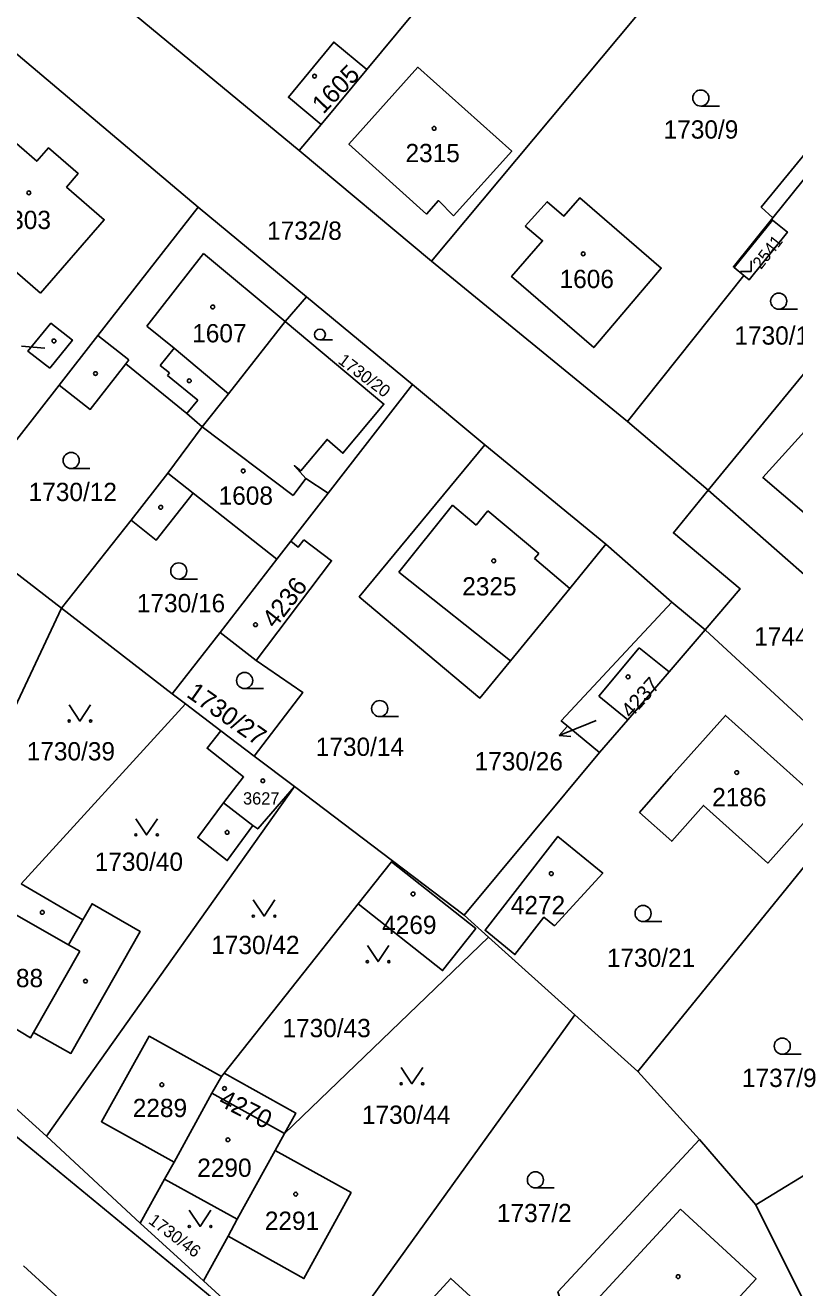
# Model space of a CAD drawing. Extents: x -679220 to -673243, y -1075091 to -1066557.
# Drawn here: x -676820 to -676748.4, y -1072173.6 to -1072056.2 of the extents above; entities that cross this region are included whole.
import ezdxf

# ---------------------------------------------------------------- set-up
doc = ezdxf.new("R2010")
doc.units = 0
for name, color, linetype in [('Hranice parcel', 7, 'Continuous'), ('Parcelní čísla', 7, 'Continuous'), ('Pop  PČ popisy', 7, 'Continuous'), ('Vnitřní kresba', 7, 'Continuous'), ('Značky budov', 7, 'Continuous'), ('Značky kultur', 7, 'Continuous')]:
    doc.layers.add(name, color=color, linetype=linetype)

msp = doc.modelspace()

# ---------------------------------------------------------------- linework, layer by layer
at = {"layer": 'Hranice parcel'}
for p, q in [((-676788.19, -1072060.27), (-676771.27, -1072039.91)), ((-676817.98, -1072048.36), (-676794.47, -1072067.82)), ((-676758.23, -1072049.49), (-676782.15, -1072078.09)), ((-676803.88, -1072073.07), (-676823.88, -1072056.2)), ((-676792.44, -1072065.38), (-676788.19, -1072060.27)), ((-676794.47, -1072067.82), (-676792.44, -1072065.38)), ((-676782.15, -1072078.09), (-676794.47, -1072067.82)), ((-676756.41, -1072099.41), (-676731.81, -1072069.41)), ((-676793.78, -1072081.41), (-676803.88, -1072073.07)), ((-676782.15, -1072078.09), (-676763.93, -1072093.01)), ((-676753.99, -1072078.69), (-676753.11, -1072079.43)), ((-676763.93, -1072093.01), (-676753.11, -1072079.43)), ((-676795.79, -1072083.71), (-676793.78, -1072081.41)), ((-676783.94, -1072089.58), (-676793.78, -1072081.41)), ((-676816.81, -1072089.62), (-676826.85, -1072102.46)), ((-676783.94, -1072089.58), (-676791.77, -1072099.66)), ((-676777.21, -1072095.19), (-676783.94, -1072089.58)), ((-676763.93, -1072093.01), (-676756.41, -1072099.41)), ((-676765.93, -1072104.41), (-676777.21, -1072095.19)), ((-676795.25, -1072104.15), (-676791.77, -1072099.66)), ((-676741.94, -1072112.1), (-676756.41, -1072099.41)), ((-676816.58, -1072110.38), (-676810.12, -1072102.18)), ((-676796.54, -1072105.8), (-676795.25, -1072104.15)), ((-676759.8, -1072109.8), (-676765.93, -1072104.41)), ((-676823.82, -1072104.8), (-676816.58, -1072110.38)), ((-676801.84, -1072112.62), (-676796.54, -1072105.8)), ((-676826.54, -1072131.48), (-676816.58, -1072110.38)), ((-676806.29, -1072118.35), (-676816.58, -1072110.38)), ((-676756.69, -1072112.4), (-676759.8, -1072109.8)), ((-676806.29, -1072118.35), (-676801.84, -1072112.62)), ((-676798.47, -1072115.23), (-676801.84, -1072112.62)), ((-676756.69, -1072112.4), (-676760.05, -1072116.28)), ((-676756.69, -1072112.4), (-676746.59, -1072121.71)), ((-676766.59, -1072118.56), (-676762.84, -1072114.06)), ((-676762.84, -1072114.06), (-676760.05, -1072116.28)), ((-676760.05, -1072116.28), (-676763.9, -1072120.74)), ((-676805.06, -1072119.28), (-676806.29, -1072118.35)), ((-676763.9, -1072120.74), (-676766.59, -1072118.56)), ((-676820.33, -1072136.02), (-676805.06, -1072119.28)), ((-676801.77, -1072121.78), (-676805.06, -1072119.28)), ((-676763.9, -1072120.74), (-676766.54, -1072123.79)), ((-676801.77, -1072121.78), (-676798.65, -1072124.14)), ((-676798.65, -1072124.14), (-676794.91, -1072126.97)), ((-676779.12, -1072138.92), (-676766.54, -1072123.79)), ((-676762.97, -1072153.46), (-676741.21, -1072126.67)), ((-676817.98, -1072159.47), (-676794.91, -1072126.97)), ((-676785.8, -1072133.86), (-676794.91, -1072126.97)), ((-676788.98, -1072137.87), (-676785.88, -1072133.96)), ((-676785.88, -1072133.96), (-676785.8, -1072133.86)), ((-676779.12, -1072138.92), (-676785.8, -1072133.86)), ((-676793.27, -1072182.15), (-676848.37, -1072136.87)), ((-676801.46, -1072153.6), (-676788.98, -1072137.87)), ((-676776.86, -1072140.96), (-676779.12, -1072138.92)), ((-676776.86, -1072140.96), (-676795.85, -1072159.22)), ((-676768.83, -1072148.2), (-676776.86, -1072140.96)), ((-676793.27, -1072182.15), (-676768.83, -1072148.2)), ((-676762.97, -1072153.46), (-676768.83, -1072148.2)), ((-676751.97, -1072165.85), (-676723.6, -1072148.5)), ((-676817.98, -1072159.47), (-676828.45, -1072150.07)), ((-676802.59, -1072155.49), (-676801.71, -1072153.92)), ((-676801.71, -1072153.92), (-676801.46, -1072153.6)), ((-676757.22, -1072159.8), (-676762.97, -1072153.46)), ((-676806.12, -1072161.88), (-676802.59, -1072155.49)), ((-676795.85, -1072159.22), (-676802.59, -1072155.49)), ((-676809.27, -1072167.56), (-676817.98, -1072159.47)), ((-676796.72, -1072160.8), (-676795.85, -1072159.22)), ((-676751.97, -1072165.85), (-676757.22, -1072159.8)), ((-676800.24, -1072167.19), (-676796.72, -1072160.8)), ((-676806.12, -1072161.88), (-676807, -1072163.46)), ((-676809.27, -1072167.56), (-676807, -1072163.46)), ((-676807, -1072163.46), (-676800.24, -1072167.19)), ((-676743.31, -1072183.24), (-676751.97, -1072165.85)), ((-676803.37, -1072172.94), (-676809.27, -1072167.56)), ((-676800.24, -1072167.19), (-676801.09, -1072168.79)), ((-676801.09, -1072168.79), (-676803.37, -1072172.94)), ((-676820.13, -1072171.54), (-676804.75, -1072185.58)), ((-676793.27, -1072182.15), (-676803.37, -1072172.94))]:
    msp.add_line(p, q, dxfattribs=at)
for points in [[(-676750.39, -1072074.06), (-676751.47, -1072073.09), (-676735.26, -1072053.27)], [(-676788.19, -1072060.27), (-676791.25, -1072057.73), (-676795.48, -1072062.86), (-676792.44, -1072065.38)], [(-676780.12, -1072073.89), (-676774.69, -1072067.86), (-676783.42, -1072060.07), (-676789.85, -1072067.21), (-676782.64, -1072073.72), (-676781.52, -1072072.47), (-676780.12, -1072073.89)], [(-676738.78, -1072062.18), (-676740, -1072061.16), (-676750.39, -1072074.06)], [(-676818.55, -1072081.08), (-676812.62, -1072074.24), (-676816.12, -1072071.21), (-676815.04, -1072069.96), (-676817.81, -1072067.56), (-676818.89, -1072068.81), (-676822.18, -1072065.95), (-676825.37, -1072069.64), (-676823.93, -1072070.88), (-676826.67, -1072074.03), (-676818.55, -1072081.08)], [(-676773.44, -1072074.83), (-676771.82, -1072076.2), (-676774.7, -1072079.53), (-676767.06, -1072086.14), (-676760.78, -1072078.74), (-676768.37, -1072072.21), (-676769.84, -1072073.91), (-676771.39, -1072072.57), (-676773.44, -1072074.83)], [(-676803.88, -1072073.07), (-676813.22, -1072085.02), (-676816.81, -1072089.62)], [(-676753.99, -1072078.69), (-676754.07, -1072078.63), (-676750.39, -1072074.06)], [(-676753.11, -1072079.43), (-676752.59, -1072079.83), (-676749.04, -1072075.39), (-676750.43, -1072074.27), (-676753.99, -1072078.69)], [(-676817.68, -1072088.06), (-676815.58, -1072085.43), (-676817.58, -1072083.87), (-676819.71, -1072086.47), (-676817.68, -1072088.06)], [(-676803.49, -1072093.51), (-676801.06, -1072090.45), (-676795.79, -1072083.71)], [(-676791.77, -1072099.66), (-676793.84, -1072098.3), (-676794.91, -1072097.12), (-676794.33, -1072097.61), (-676791.87, -1072094.68), (-676790.4, -1072095.96), (-676786.59, -1072091.39), (-676795.79, -1072083.71)], [(-676816.81, -1072089.62), (-676813.91, -1072091.88), (-676810.61, -1072087.65), (-676804.93, -1072092.28), (-676803.49, -1072093.51)], [(-676740.5, -1072105.16), (-676736.38, -1072098.43), (-676745.06, -1072091.31), (-676751.32, -1072098.22), (-676743.64, -1072104.78), (-676742.41, -1072103.46), (-676740.5, -1072105.16)], [(-676803.49, -1072093.51), (-676806.69, -1072097.82), (-676810.12, -1072102.18)], [(-676777.21, -1072095.19), (-676788.88, -1072109.31), (-676777.65, -1072118.73), (-676774.81, -1072115.26), (-676769.3, -1072108.53), (-676765.93, -1072104.41)], [(-676810.12, -1072102.18), (-676807.77, -1072104.03), (-676804.33, -1072099.67), (-676796.54, -1072105.8)], [(-676756.41, -1072099.41), (-676759.65, -1072103.37), (-676753.44, -1072108.56), (-676756.69, -1072112.4)], [(-676794.04, -1072104), (-676791.45, -1072105.96), (-676798.47, -1072115.23)], [(-676795.25, -1072104.15), (-676794.56, -1072104.69), (-676794.04, -1072104)], [(-676766.54, -1072123.79), (-676770.08, -1072120.85), (-676759.8, -1072109.8)], [(-676798.47, -1072115.23), (-676794.13, -1072118.22), (-676798.65, -1072124.14)], [(-676762.8, -1072129.36), (-676759.8, -1072132.05), (-676756.85, -1072128.71), (-676750.87, -1072134.07), (-676745.81, -1072128.41), (-676754.79, -1072120.35), (-676759.86, -1072125.98), (-676762.8, -1072129.36)], [(-676794.91, -1072126.97), (-676798.33, -1072130.9), (-676798.8, -1072130.59), (-676801.17, -1072133.85), (-676803.91, -1072131.7), (-676801.51, -1072128.46), (-676799.64, -1072126.06), (-676803.05, -1072123.4), (-676801.77, -1072121.78)], [(-676770.7, -1072139.91), (-676771.7, -1072139.11), (-676774.4, -1072142.59), (-676777.17, -1072140.32), (-676770.39, -1072131.6), (-676766.22, -1072135.01), (-676770.7, -1072139.91)], [(-676785.88, -1072133.96), (-676778.03, -1072140.17), (-676781.13, -1072144.08), (-676788.98, -1072137.87)], [(-676826.29, -1072146.21), (-676819.47, -1072150.32), (-676819.19, -1072149.82), (-676815.71, -1072151.78), (-676809.26, -1072140.45), (-676813.74, -1072137.86), (-676814.6, -1072139.34), (-676820.33, -1072136.02)], [(-676801.71, -1072153.92), (-676808.44, -1072150.18), (-676812.87, -1072158.13), (-676806.12, -1072161.88)], [(-676795.85, -1072159.22), (-676794.8, -1072157.32), (-676801.46, -1072153.6)], [(-676782.19, -1072193.53), (-676768.8, -1072178.75), (-676770.39, -1072173.95), (-676757.22, -1072159.8)], [(-676801.09, -1072168.79), (-676794.04, -1072172.72), (-676789.65, -1072164.72), (-676796.72, -1072160.8)], [(-676758.98, -1072166.26), (-676766.77, -1072174.7), (-676759.74, -1072181.19), (-676751.95, -1072172.75), (-676758.98, -1072166.26)], [(-676784.15, -1072176.83), (-676785.33, -1072175.75), (-676787.35, -1072177.96), (-676786.17, -1072179.04), (-676787.94, -1072180.97), (-676781.01, -1072187.31), (-676773.44, -1072179.04), (-676780.37, -1072172.7), (-676784.15, -1072176.83)]]:
    msp.add_lwpolyline(points, dxfattribs=at)
at = {"layer": 'Pop  PČ popisy'}
for p, q in [((-676818.14, -1072086.2), (-676820.32, -1072086.01)), ((-676766.83, -1072120.81), (-676767.51, -1072121.09)), ((-676767.51, -1072121.09), (-676770.29, -1072122.21)), ((-676770.29, -1072122.21), (-676769.55, -1072121.38)), ((-676770.29, -1072122.21), (-676769.18, -1072122.3))]:
    msp.add_line(p, q, dxfattribs=at)
at = {"layer": 'Vnitřní kresba'}
for p, q in [((-676803.38, -1072077.4), (-676808.65, -1072084.13)), ((-676795.79, -1072083.71), (-676803.38, -1072077.4)), ((-676808.65, -1072084.13), (-676806.11, -1072086.2)), ((-676813.22, -1072085.02), (-676810.32, -1072087.28)), ((-676806.11, -1072086.2), (-676807.4, -1072087.79)), ((-676806.11, -1072086.2), (-676801.06, -1072090.45)), ((-676810.32, -1072087.28), (-676810.61, -1072087.65)), ((-676807.4, -1072087.79), (-676806.55, -1072088.49)), ((-676806.55, -1072088.49), (-676806.74, -1072088.72)), ((-676806.74, -1072088.72), (-676803.91, -1072091.03)), ((-676803.91, -1072091.03), (-676804.93, -1072092.28)), ((-676803.49, -1072093.51), (-676795.03, -1072099.88)), ((-676806.69, -1072097.82), (-676804.33, -1072099.67)), ((-676795.03, -1072099.88), (-676793.84, -1072098.3)), ((-676785.19, -1072107.02), (-676780.21, -1072100.8)), ((-676780.21, -1072100.8), (-676777.99, -1072102.65)), ((-676777.99, -1072102.65), (-676776.91, -1072101.33)), ((-676776.91, -1072101.33), (-676772.16, -1072105.29)), ((-676772.16, -1072105.29), (-676772.56, -1072105.74)), ((-676772.56, -1072105.74), (-676769.3, -1072108.53)), ((-676774.81, -1072115.26), (-676785.19, -1072107.02)), ((-676801.51, -1072128.46), (-676798.8, -1072130.59)), ((-676821.85, -1072138.29), (-676815.95, -1072141.68)), ((-676815.95, -1072141.68), (-676814.6, -1072139.34)), ((-676814.9, -1072142.28), (-676815.95, -1072141.68)), ((-676819.19, -1072149.82), (-676814.9, -1072142.28))]:
    msp.add_line(p, q, dxfattribs=at)
at = {"layer": 'Značky budov'}
for centre in [(-676793.04, -1072060.89), (-676781.92, -1072065.75), (-676819.63, -1072071.74), (-676768.04, -1072077.42), (-676802.52, -1072082.36), (-676817.29, -1072085.52), (-676813.43, -1072088.55), (-676804.7, -1072089.22), (-676799.68, -1072097.61), (-676807.36, -1072100.99), (-676776.37, -1072105.97), (-676798.54, -1072111.91), (-676763.87, -1072116.76), (-676753.76, -1072125.66), (-676797.86, -1072126.42), (-676801.18, -1072131.22), (-676771.01, -1072135.06), (-676783.88, -1072136.95), (-676818.38, -1072138.66), (-676814.36, -1072145.05), (-676807.25, -1072154.69), (-676801.42, -1072155.04), (-676801.1, -1072159.81), (-676794.8, -1072164.87), (-676759.21, -1072172.54)]:
    msp.add_circle(centre, 0.175, dxfattribs=at)
at = {"layer": 'Značky kultur'}
for p, q in [((-676757.1, -1072063.68), (-676755.35, -1072063.68)), ((-676752.42, -1072079.07), (-676752.42, -1072078.07)), ((-676753.42, -1072079.07), (-676752.42, -1072079.07)), ((-676749.85, -1072082.57), (-676748.1, -1072082.57)), ((-676792.54, -1072085.42), (-676791.36, -1072085.42)), ((-676815.69, -1072097.38), (-676813.94, -1072097.38)), ((-676805.68, -1072107.66), (-676803.93, -1072107.66)), ((-676799.55, -1072117.85), (-676797.8, -1072117.85)), ((-676786.98, -1072120.46), (-676785.23, -1072120.46)), ((-676762.47, -1072139.51), (-676760.72, -1072139.51)), ((-676749.52, -1072151.85), (-676747.77, -1072151.85)), ((-676772.49, -1072164.29), (-676770.74, -1072164.29))]:
    msp.add_line(p, q, dxfattribs=at)
for points in [[(-676815.88, -1072119.37), (-676814.88, -1072120.87), (-676813.88, -1072119.37)], [(-676809.67, -1072129.95), (-676808.67, -1072131.45), (-676807.67, -1072129.95)], [(-676798.74, -1072137.51), (-676797.74, -1072139.01), (-676796.74, -1072137.51)], [(-676788.13, -1072141.74), (-676787.13, -1072143.24), (-676786.13, -1072141.74)], [(-676784.98, -1072153.1), (-676783.98, -1072154.6), (-676782.98, -1072153.1)], [(-676804.7, -1072166.37), (-676803.7, -1072167.87), (-676802.7, -1072166.37)]]:
    msp.add_lwpolyline(points, dxfattribs=at)
for centre, radius in [((-676757.1, -1072062.93), 0.75), ((-676749.85, -1072081.82), 0.75), ((-676792.54, -1072084.92), 0.502), ((-676815.69, -1072096.63), 0.75), ((-676805.68, -1072106.91), 0.75), ((-676799.55, -1072117.1), 0.75), ((-676786.98, -1072119.71), 0.75), ((-676815.88, -1072120.87), 0.1), ((-676813.88, -1072120.87), 0.1), ((-676809.67, -1072131.45), 0.1), ((-676807.67, -1072131.45), 0.1), ((-676762.47, -1072138.76), 0.75), ((-676798.74, -1072139.01), 0.1), ((-676796.74, -1072139.01), 0.1), ((-676788.13, -1072143.24), 0.1), ((-676786.13, -1072143.24), 0.1), ((-676749.52, -1072151.1), 0.75), ((-676784.98, -1072154.6), 0.1), ((-676782.98, -1072154.6), 0.1), ((-676772.49, -1072163.54), 0.75), ((-676804.7, -1072167.87), 0.1), ((-676802.7, -1072167.87), 0.1)]:
    msp.add_circle(centre, radius, dxfattribs=at)

# ---------------------------------------------------------------- texts
at = {"layer": 'Parcelní čísla'}
for s, height, rotation, p in [('1605', 1.7, 46, (-676792.23, -1072064.49)), ('2541', 1.14, 52, (-676751.49, -1072078.93)), ('1730/20', 1.14, 323, (-676790.94, -1072087.52)), ('4236', 1.7, 52, (-676796.73, -1072112.33)), ('1730/27', 1.7, 325, (-676805.05, -1072118.55)), ('4237', 1.4, 48, (-676763.6, -1072120.68)), ('4270', 1.7, 333, (-676802.08, -1072156.56)), ('1730/46', 1.14, 323, (-676808.58, -1072167.51))]:
    msp.add_text(s, height=height, rotation=rotation, dxfattribs=at).set_placement(p)
for s, height, p in [('1730/9', 1.7, (-676760.56, -1072066.7)), ('2315', 1.7, (-676784.58, -1072068.89)), ('2303', 1.7, (-676822.63, -1072075.11)), ('1732/8', 1.7, (-676797.46, -1072076.11)), ('1606', 1.7, (-676770.24, -1072080.6)), ('1607', 1.7, (-676804.43, -1072085.65)), ('1730/13', 1.7, (-676753.97, -1072085.86)), ('1730/12', 1.7, (-676819.65, -1072100.41)), ('1608', 1.7, (-676801.97, -1072100.75)), ('2325', 1.7, (-676779.3, -1072109.19)), ('1730/16', 1.7, (-676809.58, -1072110.75)), ('1744/3', 1.7, (-676752.13, -1072113.85)), ('1730/39', 1.7, (-676819.83, -1072124.53)), ('1730/14', 1.7, (-676792.93, -1072124.11)), ('1730/26', 1.7, (-676778.15, -1072125.46)), ('3627', 1.14, (-676799.7, -1072128.63)), ('2186', 1.7, (-676756.04, -1072128.79)), ('1730/40', 1.7, (-676813.5, -1072134.8)), ('4272', 1.7, (-676774.78, -1072138.84)), ('4269', 1.7, (-676786.75, -1072140.67)), ('1730/42', 1.7, (-676802.66, -1072142.54)), ('1730/21', 1.7, (-676765.84, -1072143.73)), ('2288', 1.7, (-676823.36, -1072145.62)), ('1730/43', 1.7, (-676796.03, -1072150.27)), ('1737/9', 1.7, (-676753.27, -1072154.9)), ('2289', 1.7, (-676809.96, -1072157.7)), ('1730/44', 1.7, (-676788.63, -1072158.33)), ('2290', 1.7, (-676803.96, -1072163.26)), ('2291', 1.7, (-676797.67, -1072168.19)), ('1737/2', 1.7, (-676776.07, -1072167.47))]:
    msp.add_text(s, height=height, dxfattribs=at).set_placement(p)

doc.saveas('drawing.dxf')
